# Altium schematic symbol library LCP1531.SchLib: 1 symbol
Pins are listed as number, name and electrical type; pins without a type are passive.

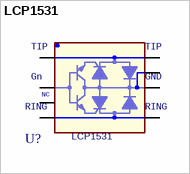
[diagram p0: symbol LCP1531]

## LCP1531
designator U?
footprint ST_SO8
pins: 1 TIP, 2 Gn, 3 NC, 4 RING, 5 RING1, 6 GND, 7 GND1, 8 TIP1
